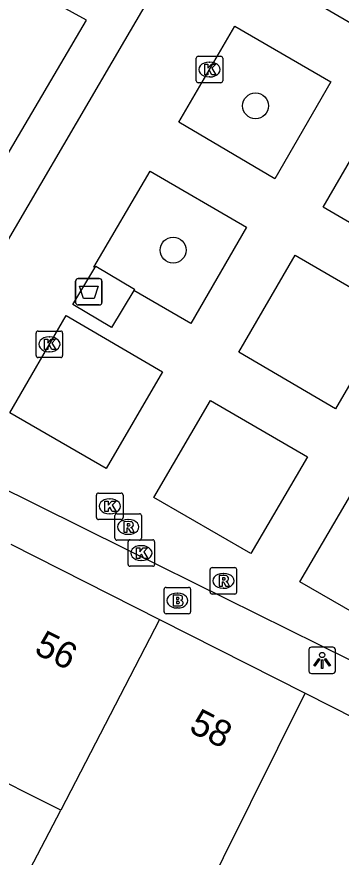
# Model space of a CAD drawing. Extents: x 160664 to 161506, y 382245 to 383288.
# Drawn here: x 161037.82 to 161050.06, y 383083.11 to 383114.86 of the extents above; entities that cross this region are included whole.
import ezdxf

# ---------------------------------------------------------------- set-up
doc = ezdxf.new("R2010")
doc.units = 0
for name, color, linetype in [('IMGEO_Afval_apart_plaats', 7, 'Continuous'), ('IMGEO_Boom', 7, 'Continuous'), ('IMGEO_Brandkraan', 7, 'Continuous'), ('IMGEO_Kolk', 7, 'Continuous'), ('IMGEO_Lichtpunt', 7, 'Continuous'), ('IMGEO_Pand', 7, 'Continuous'), ('IMGEO_Pand_nummerreeks', 7, 'Continuous'), ('IMGEO_Pand_overbouw', 7, 'Continuous'), ('IMGEO_Rijbaan_lokaal_open', 7, 'Continuous'), ('IMGEO_Rioolput', 7, 'Continuous'), ('IMGEO_Voetpad_gesloten', 7, 'Continuous'), ('IMGEO_Voetpad_open', 7, 'Continuous')]:
    doc.layers.add(name, color=color, linetype=linetype)

msp = doc.modelspace()

# ---------------------------------------------------------------- linework, layer by layer
at = {"layer": 'IMGEO_Afval_apart_plaats'}
for p, q in [((161040.039, 383104.074), (161040.039, 383104.874)), ((161040.039, 383104.874), (161040.039, 383104.074)), ((161040.139, 383104.974), (161040.929, 383104.974)), ((161040.929, 383104.974), (161040.139, 383104.974)), ((161041.029, 383104.874), (161041.029, 383104.074)), ((161041.029, 383104.074), (161041.029, 383104.874)), ((161040.929, 383103.974), (161040.139, 383103.974)), ((161040.139, 383103.974), (161040.929, 383103.974))]:
    msp.add_line(p, q, dxfattribs=at)
msp.add_lwpolyline([(161040.182, 383104.688), (161040.886, 383104.688), (161040.737, 383104.218), (161040.331, 383104.218), (161040.182, 383104.688)], dxfattribs=at)
for centre, start, end in [((161040.139, 383104.874), 90, 180), ((161040.139, 383104.874), 90, 180), ((161040.929, 383104.874), 0, 90), ((161040.929, 383104.874), 360, 90), ((161040.139, 383104.074), 180, 270), ((161040.139, 383104.074), 180, 270), ((161040.929, 383104.074), 270, 0), ((161040.929, 383104.074), 270, 0)]:
    msp.add_arc(centre, 0.1, start, end, dxfattribs=at)
at = {"layer": 'IMGEO_Boom'}
for centre in [(161046.826, 383111.499), (161043.718, 383106.048)]:
    msp.add_circle(centre, 0.489, dxfattribs=at)
at = {"layer": 'IMGEO_Brandkraan'}
for p, q in [((161043.45, 383093.305), (161044.302, 383093.305)), ((161043.375, 383092.379), (161043.375, 383093.231)), ((161043.863, 383093.085), (161043.888, 383093.085)), ((161044.376, 383093.231), (161044.376, 383092.379)), ((161044.302, 383092.305), (161043.45, 383092.305)), ((161043.886, 383092.525), (161043.861, 383092.525))]:
    msp.add_line(p, q, dxfattribs=at)
for points in [[(161043.45, 383093.305), (161044.302, 383093.305)], [(161043.375, 383092.379), (161043.375, 383093.231)], [(161043.723, 383093.005), (161043.723, 383092.605), (161043.936, 383092.605)], [(161043.954, 383093.005), (161043.723, 383093.005)], [(161044.376, 383093.231), (161044.376, 383092.379)], [(161043.902, 383092.924), (161043.848, 383092.924), (161043.848, 383092.848)], [(161043.848, 383092.848), (161043.901, 383092.848)], [(161043.91, 383092.772), (161043.848, 383092.772), (161043.848, 383092.691)], [(161043.848, 383092.691), (161043.91, 383092.691)], [(161044.302, 383092.305), (161043.45, 383092.305)]]:
    msp.add_lwpolyline(points, dxfattribs=at)
for centre, radius, start, end in [((161043.452, 383093.229), 0.0765, 91.552, 178.448), ((161043.452, 383093.229), 0.0765, 91.552, 178.448), ((161044.3, 383093.229), 0.0765, 1.552, 88.448), ((161044.3, 383093.229), 0.0765, 1.552, 88.448), ((161043.958, 383092.86), 0.145, 59.4692, 91.5367), ((161043.983, 383092.907), 0.0922, 285.5137, 58.1501), ((161043.903, 383092.886), 0.0379, 267.8285, 90.9355), ((161043.911, 383092.731), 0.0404, 269.8759, 90.5077), ((161043.942, 383092.856), 0.251, 268.6676, 293.5347), ((161043.988, 383092.715), 0.105, 301.3115, 78.989), ((161043.452, 383092.381), 0.0765, 181.552, 268.448), ((161043.452, 383092.381), 0.0765, 181.552, 268.448), ((161044.3, 383092.381), 0.0765, 271.552, 358.448), ((161044.3, 383092.381), 0.0765, 271.552, 358.448)]:
    msp.add_arc(centre, radius, start, end, dxfattribs=at)
for centre, major_axis, ratio, start_param, end_param in [((161043.862, 383092.805), (-0.387, 0.002), 0.722429, 4.712389, 7.853982), ((161043.887, 383092.805), (-0.39, 0.002), 0.717154, 1.570796, 4.712389)]:
    msp.add_ellipse(centre, major_axis=major_axis, ratio=ratio, start_param=start_param, end_param=end_param, dxfattribs=at)
at = {"layer": 'IMGEO_Kolk'}
for p, q in [((161044.587, 383112.445), (161044.587, 383113.297)), ((161044.662, 383113.371), (161045.514, 383113.371)), ((161045.588, 383113.297), (161045.588, 383112.445)), ((161045.075, 383113.151), (161045.1, 383113.151)), ((161045.514, 383112.371), (161044.662, 383112.371)), ((161045.098, 383112.591), (161045.073, 383112.591)), ((161038.547, 383102.062), (161038.547, 383102.914)), ((161038.622, 383102.988), (161039.474, 383102.988)), ((161039.548, 383102.914), (161039.548, 383102.062)), ((161039.035, 383102.768), (161039.06, 383102.768)), ((161039.058, 383102.208), (161039.033, 383102.208)), ((161039.474, 383101.988), (161038.622, 383101.988)), ((161040.825, 383095.941), (161040.825, 383096.793)), ((161040.9, 383096.867), (161041.752, 383096.867)), ((161041.826, 383096.793), (161041.826, 383095.941)), ((161041.313, 383096.647), (161041.338, 383096.647)), ((161041.752, 383095.867), (161040.9, 383095.867)), ((161041.336, 383096.087), (161041.311, 383096.087)), ((161042.018, 383094.174), (161042.018, 383095.026)), ((161042.093, 383095.1), (161042.945, 383095.1)), ((161042.506, 383094.88), (161042.531, 383094.88)), ((161043.019, 383095.026), (161043.019, 383094.174)), ((161042.529, 383094.32), (161042.504, 383094.32)), ((161042.945, 383094.1), (161042.093, 383094.1))]:
    msp.add_line(p, q, dxfattribs=at)
for points in [[(161044.587, 383112.445), (161044.587, 383113.297)], [(161044.662, 383113.371), (161045.514, 383113.371)], [(161045.588, 383113.297), (161045.588, 383112.445)], [(161044.908, 383113.071), (161045.031, 383113.071), (161045.031, 383112.92), (161045.161, 383113.071), (161045.325, 383113.071), (161045.179, 383112.92), (161045.332, 383112.671), (161045.18, 383112.671), (161045.095, 383112.835), (161045.031, 383112.768), (161045.031, 383112.671), (161044.908, 383112.671), (161044.908, 383113.071)], [(161045.514, 383112.371), (161044.662, 383112.371)], [(161038.547, 383102.062), (161038.547, 383102.914)], [(161038.622, 383102.988), (161039.474, 383102.988)], [(161039.548, 383102.914), (161039.548, 383102.062)], [(161038.868, 383102.688), (161038.991, 383102.688), (161038.991, 383102.537), (161039.121, 383102.688), (161039.285, 383102.688), (161039.139, 383102.537), (161039.292, 383102.288), (161039.14, 383102.288), (161039.055, 383102.452), (161038.991, 383102.385), (161038.991, 383102.288), (161038.868, 383102.288), (161038.868, 383102.688)], [(161039.474, 383101.988), (161038.622, 383101.988)], [(161040.825, 383095.941), (161040.825, 383096.793)], [(161040.9, 383096.867), (161041.752, 383096.867)], [(161041.826, 383096.793), (161041.826, 383095.941)], [(161041.146, 383096.567), (161041.269, 383096.567), (161041.269, 383096.416), (161041.399, 383096.567), (161041.563, 383096.567), (161041.417, 383096.416), (161041.57, 383096.167), (161041.418, 383096.167), (161041.333, 383096.331), (161041.269, 383096.264), (161041.269, 383096.167), (161041.146, 383096.167), (161041.146, 383096.567)], [(161041.752, 383095.867), (161040.9, 383095.867)], [(161042.018, 383094.174), (161042.018, 383095.026)], [(161042.093, 383095.1), (161042.945, 383095.1)], [(161043.019, 383095.026), (161043.019, 383094.174)], [(161042.339, 383094.8), (161042.462, 383094.8), (161042.462, 383094.649), (161042.592, 383094.8), (161042.756, 383094.8), (161042.61, 383094.649), (161042.763, 383094.4), (161042.611, 383094.4), (161042.526, 383094.564), (161042.462, 383094.497), (161042.462, 383094.4), (161042.339, 383094.4), (161042.339, 383094.8)], [(161042.945, 383094.1), (161042.093, 383094.1)]]:
    msp.add_lwpolyline(points, dxfattribs=at)
for centre, start, end in [((161044.664, 383113.295), 91.552, 178.448), ((161044.664, 383113.295), 91.552, 178.448), ((161045.512, 383113.295), 1.552, 88.448), ((161045.512, 383113.295), 1.552, 88.448), ((161044.664, 383112.447), 181.552, 268.448), ((161044.664, 383112.447), 181.552, 268.448), ((161045.512, 383112.447), 271.552, 358.448), ((161045.512, 383112.447), 271.552, 358.448), ((161038.624, 383102.912), 91.552, 178.448), ((161038.624, 383102.912), 91.552, 178.448), ((161039.472, 383102.912), 1.552, 88.448), ((161039.472, 383102.912), 1.552, 88.448), ((161038.624, 383102.064), 181.552, 268.448), ((161038.624, 383102.064), 181.552, 268.448), ((161039.472, 383102.064), 271.552, 358.448), ((161039.472, 383102.064), 271.552, 358.448), ((161040.902, 383096.791), 91.552, 178.448), ((161040.902, 383096.791), 91.552, 178.448), ((161041.75, 383096.791), 1.552, 88.448), ((161041.75, 383096.791), 1.552, 88.448), ((161040.902, 383095.943), 181.552, 268.448), ((161040.902, 383095.943), 181.552, 268.448), ((161041.75, 383095.943), 271.552, 358.448), ((161041.75, 383095.943), 271.552, 358.448), ((161042.095, 383095.024), 91.552, 178.448), ((161042.095, 383095.024), 91.552, 178.448), ((161042.943, 383095.024), 1.552, 88.448), ((161042.943, 383095.024), 1.552, 88.448), ((161042.095, 383094.176), 181.552, 268.448), ((161042.095, 383094.176), 181.552, 268.448), ((161042.943, 383094.176), 271.552, 358.448), ((161042.943, 383094.176), 271.552, 358.448)]:
    msp.add_arc(centre, 0.0765, start, end, dxfattribs=at)
for centre, major_axis, ratio, start_param, end_param in [((161045.074, 383112.871), (-0.387, 0.002), 0.722429, 4.712389, 7.853982), ((161045.099, 383112.871), (-0.39, 0.002), 0.717154, 1.570796, 4.712389), ((161039.034, 383102.488), (-0.387, 0.002), 0.722429, 4.712389, 7.853982), ((161039.059, 383102.488), (-0.39, 0.002), 0.717154, 1.570796, 4.712389), ((161041.312, 383096.367), (-0.387, 0.002), 0.722429, 4.712389, 7.853982), ((161041.337, 383096.367), (-0.39, 0.002), 0.717154, 1.570796, 4.712389), ((161042.505, 383094.6), (-0.387, 0.002), 0.722429, 4.712389, 7.853982), ((161042.53, 383094.6), (-0.39, 0.002), 0.717154, 1.570796, 4.712389)]:
    msp.add_ellipse(centre, major_axis=major_axis, ratio=ratio, start_param=start_param, end_param=end_param, dxfattribs=at)
at = {"layer": 'IMGEO_Lichtpunt'}
for p, q in [((161049.743, 383091.046), (161048.935, 383091.046)), ((161049.743, 383091.046), (161048.935, 383091.046)), ((161048.841, 383090.951), (161048.841, 383090.144)), ((161048.841, 383090.951), (161048.841, 383090.144)), ((161049.837, 383090.144), (161049.837, 383090.951)), ((161049.837, 383090.144), (161049.837, 383090.951)), ((161048.935, 383090.05), (161049.743, 383090.05)), ((161048.935, 383090.05), (161049.743, 383090.05))]:
    msp.add_line(p, q, dxfattribs=at)
for points in [[(161049.215, 383090.615), (161049.254, 383090.587), (161049.066, 383090.325), (161049.028, 383090.352), (161049.215, 383090.615)], [(161049.317, 383090.567), (161049.364, 383090.567), (161049.364, 383090.245), (161049.317, 383090.245), (161049.317, 383090.567)], [(161049.427, 383090.587), (161049.465, 383090.614), (161049.652, 383090.352), (161049.613, 383090.324), (161049.427, 383090.587)]]:
    msp.add_lwpolyline(points, dxfattribs=at)
msp.add_circle((161049.34, 383090.749), 0.0994, dxfattribs=at)
for centre, start, end in [((161048.935, 383090.951), 90, 180), ((161048.935, 383090.951), 90, 180), ((161049.743, 383090.951), 0, 90), ((161049.743, 383090.951), 0, 90), ((161048.935, 383090.144), 180, 270), ((161048.935, 383090.144), 180, 270), ((161049.743, 383090.144), 270, 0), ((161049.743, 383090.144), 270, 360)]:
    msp.add_arc(centre, 0.0946, start, end, dxfattribs=at)
at = {"layer": 'IMGEO_Pand'}
for points in [[(161037.593, 383094.932), (161043.206, 383092.086)], [(161043.206, 383092.086), (161039.474, 383084.886)], [(161043.206, 383092.086), (161048.694, 383089.304)], [(161043.544, 383079.113), (161044.591, 383081.024), (161048.694, 383089.304)], [(161048.694, 383089.304), (161054.43, 383086.396)], [(161039.474, 383084.886), (161036.163, 383086.554), (161034.549, 383083.349), (161032.257, 383084.503), (161033.847, 383087.611)], [(161043.544, 383079.113), (161043.275, 383078.622), (161038.351, 383081.512), (161038.012, 383081.711), (161037.871, 383081.794), (161039.474, 383084.886)]]:
    msp.add_lwpolyline(points, dxfattribs=at)
at = {"layer": 'IMGEO_Pand_overbouw'}
msp.add_lwpolyline([(161040.443, 383114.738), (161036.991, 383116.641), (161033.988, 383109.53), (161024.187, 383113.68), (161023.621, 383112.342), (161035.088, 383105.632)], close=True, dxfattribs=at)
at = {"layer": 'IMGEO_Rijbaan_lokaal_open'}
for points in [[(161049.376, 383107.667), (161051.504, 383111.331), (161055.175, 383109.213), (161053.029, 383105.542), (161049.376, 383107.667)], [(161051.978, 383103.728), (161049.841, 383100.047), (161046.2, 383102.196), (161048.325, 383105.859), (161051.978, 383103.728)], [(161041.194, 383097.79), (161037.554, 383099.898), (161039.676, 383103.575), (161043.32, 383101.445), (161041.194, 383097.79)], [(161046.653, 383094.586), (161042.995, 383096.706), (161045.126, 383100.366), (161048.789, 383098.232), (161046.653, 383094.586)], [(161054.265, 383095.062), (161052.14, 383091.41), (161048.497, 383093.517), (161050.639, 383097.169), (161054.265, 383095.062)]]:
    msp.add_lwpolyline(points, dxfattribs=at)
at = {"layer": 'IMGEO_Rioolput'}
for p, q in [((161041.52, 383095.162), (161041.52, 383096.014)), ((161041.595, 383096.088), (161042.447, 383096.088)), ((161042.008, 383095.868), (161042.033, 383095.868)), ((161042.521, 383096.014), (161042.521, 383095.162)), ((161042.031, 383095.308), (161042.006, 383095.308)), ((161042.447, 383095.088), (161041.595, 383095.088)), ((161045.113, 383093.124), (161045.113, 383093.976)), ((161045.188, 383094.05), (161046.04, 383094.05)), ((161046.114, 383093.976), (161046.114, 383093.124)), ((161045.601, 383093.83), (161045.626, 383093.83)), ((161045.624, 383093.27), (161045.599, 383093.27)), ((161046.04, 383093.05), (161045.188, 383093.05))]:
    msp.add_line(p, q, dxfattribs=at)
for points in [[(161041.52, 383095.162), (161041.52, 383096.014)], [(161041.595, 383096.088), (161042.447, 383096.088)], [(161042.521, 383096.014), (161042.521, 383095.162)], [(161042.109, 383095.786), (161041.857, 383095.788), (161041.857, 383095.388)], [(161041.857, 383095.388), (161041.981, 383095.388), (161041.981, 383095.55), (161041.992, 383095.55)], [(161042.035, 383095.707), (161041.981, 383095.707), (161041.981, 383095.626)], [(161041.981, 383095.626), (161042.033, 383095.626)], [(161042.039, 383095.521), (161042.11, 383095.388), (161042.25, 383095.388), (161042.185, 383095.514)], [(161042.447, 383095.088), (161041.595, 383095.088)], [(161045.113, 383093.124), (161045.113, 383093.976)], [(161045.188, 383094.05), (161046.04, 383094.05)], [(161046.114, 383093.976), (161046.114, 383093.124)], [(161045.702, 383093.748), (161045.45, 383093.75), (161045.45, 383093.35)], [(161045.628, 383093.669), (161045.574, 383093.669), (161045.574, 383093.588)], [(161045.574, 383093.588), (161045.626, 383093.588)], [(161045.45, 383093.35), (161045.574, 383093.35), (161045.574, 383093.512), (161045.585, 383093.512)], [(161045.632, 383093.483), (161045.703, 383093.35), (161045.843, 383093.35), (161045.778, 383093.476)], [(161046.04, 383093.05), (161045.188, 383093.05)]]:
    msp.add_lwpolyline(points, dxfattribs=at)
for centre, radius, start, end in [((161041.597, 383096.012), 0.0765, 91.552, 178.448), ((161041.597, 383096.012), 0.0765, 91.552, 178.448), ((161042.445, 383096.012), 0.0765, 1.552, 88.448), ((161042.445, 383096.012), 0.0765, 1.552, 88.448), ((161041.991, 383095.497), 0.0533, 26.0293, 88.6989), ((161042.017, 383095.815), 0.19, 274.7715, 282.9687), ((161042.041, 383095.611), 0.0964, 77.0061, 93.1865), ((161042.055, 383095.668), 0.0378, 276.6634, 79.6772), ((161042.108, 383095.676), 0.109, 350.3612, 89.416), ((161042.106, 383095.676), 0.112, 277.5842, 350.9817), ((161042.09, 383095.461), 0.108, 29.5134, 73.7905), ((161041.597, 383095.164), 0.0765, 181.552, 268.448), ((161041.597, 383095.164), 0.0765, 181.552, 268.448), ((161042.445, 383095.164), 0.0765, 271.552, 358.448), ((161042.445, 383095.164), 0.0765, 271.552, 358.448), ((161045.19, 383093.974), 0.0765, 91.552, 178.448), ((161045.19, 383093.974), 0.0765, 91.552, 178.448), ((161046.038, 383093.974), 0.0765, 1.552, 88.448), ((161046.038, 383093.974), 0.0765, 1.552, 88.448), ((161045.61, 383093.777), 0.19, 274.7715, 282.9687), ((161045.634, 383093.573), 0.0964, 77.0061, 93.1865), ((161045.648, 383093.63), 0.0378, 276.6634, 79.6772), ((161045.701, 383093.638), 0.109, 350.3612, 89.416), ((161045.699, 383093.638), 0.112, 277.5842, 350.9817), ((161045.584, 383093.459), 0.0533, 26.0293, 88.6989), ((161045.683, 383093.423), 0.108, 29.5134, 73.7905), ((161045.19, 383093.126), 0.0765, 181.552, 268.448), ((161045.19, 383093.126), 0.0765, 181.552, 268.448), ((161046.038, 383093.126), 0.0765, 271.552, 358.448), ((161046.038, 383093.126), 0.0765, 271.552, 358.448)]:
    msp.add_arc(centre, radius, start, end, dxfattribs=at)
for centre, major_axis, ratio, start_param, end_param in [((161042.007, 383095.588), (-0.387, 0.002), 0.722429, 4.712389, 7.853982), ((161042.032, 383095.588), (-0.39, 0.002), 0.717154, 1.570796, 4.712389), ((161045.6, 383093.55), (-0.387, 0.002), 0.722429, 4.712389, 7.853982), ((161045.625, 383093.55), (-0.39, 0.002), 0.717154, 1.570796, 4.712389)]:
    msp.add_ellipse(centre, major_axis=major_axis, ratio=ratio, start_param=start_param, end_param=end_param, dxfattribs=at)
at = {"layer": 'IMGEO_Voetpad_gesloten'}
for points in [[(161042.232, 383104.527), (161041.392, 383103.124), (161039.937, 383103.995), (161040.766, 383105.379)], [(161040.766, 383105.379), (161040.801, 383105.438), (161042.256, 383104.567), (161042.232, 383104.527)]]:
    msp.add_lwpolyline(points, dxfattribs=at)
at = {"layer": 'IMGEO_Voetpad_open'}
for points in [[(161058.013, 383124.181), (161051.948, 383113.731), (161047.618, 383116.259)], [(161036.411, 383104.597), (161041.893, 383113.972), (161043.178, 383116.176), (161038.659, 383118.796)], [(161047.559, 383108.746), (161043.929, 383110.885), (161046.047, 383114.511), (161049.662, 383112.405), (161047.559, 383108.746)], [(161040.766, 383105.379), (161040.728, 383105.401), (161042.854, 383109.025), (161046.487, 383106.917), (161044.383, 383103.277), (161042.232, 383104.527)], [(161053.903, 383088.811), (161045.718, 383092.869), (161041.96, 383094.732), (161033.603, 383098.876)]]:
    msp.add_lwpolyline(points, dxfattribs=at)

# ---------------------------------------------------------------- texts
at = {"layer": 'IMGEO_Pand_nummerreeks'}
for s, p in [('56', (161038.431, 383090.83)), ('58', (161044.271, 383087.87))]:
    msp.add_text(s, height=1, rotation=333.1168, dxfattribs=at).set_placement(p)

doc.saveas('drawing.dxf')
